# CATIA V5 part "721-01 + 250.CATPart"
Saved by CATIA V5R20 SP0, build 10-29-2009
Part number: 721-01 + 250
Revision: TUTTO
Definition: NON CONOSCIUTO
Nomenclature: 721-01 + 250
Source: Unknown
Bounding box of the stored display mesh (mm): x -50 to 50, y -50 to 25, z -5 to 250
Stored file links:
  C:\Users\Utente\Desktop\IO LAVORO\3D X SITO CF\X 3D SITO CF 27-09-2020\721\721-01 + 250.CATPart
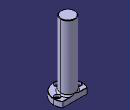
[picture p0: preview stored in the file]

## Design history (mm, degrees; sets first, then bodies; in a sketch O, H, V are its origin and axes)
Body1 "Smusso4" (main body)
  Solid1: solid without history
